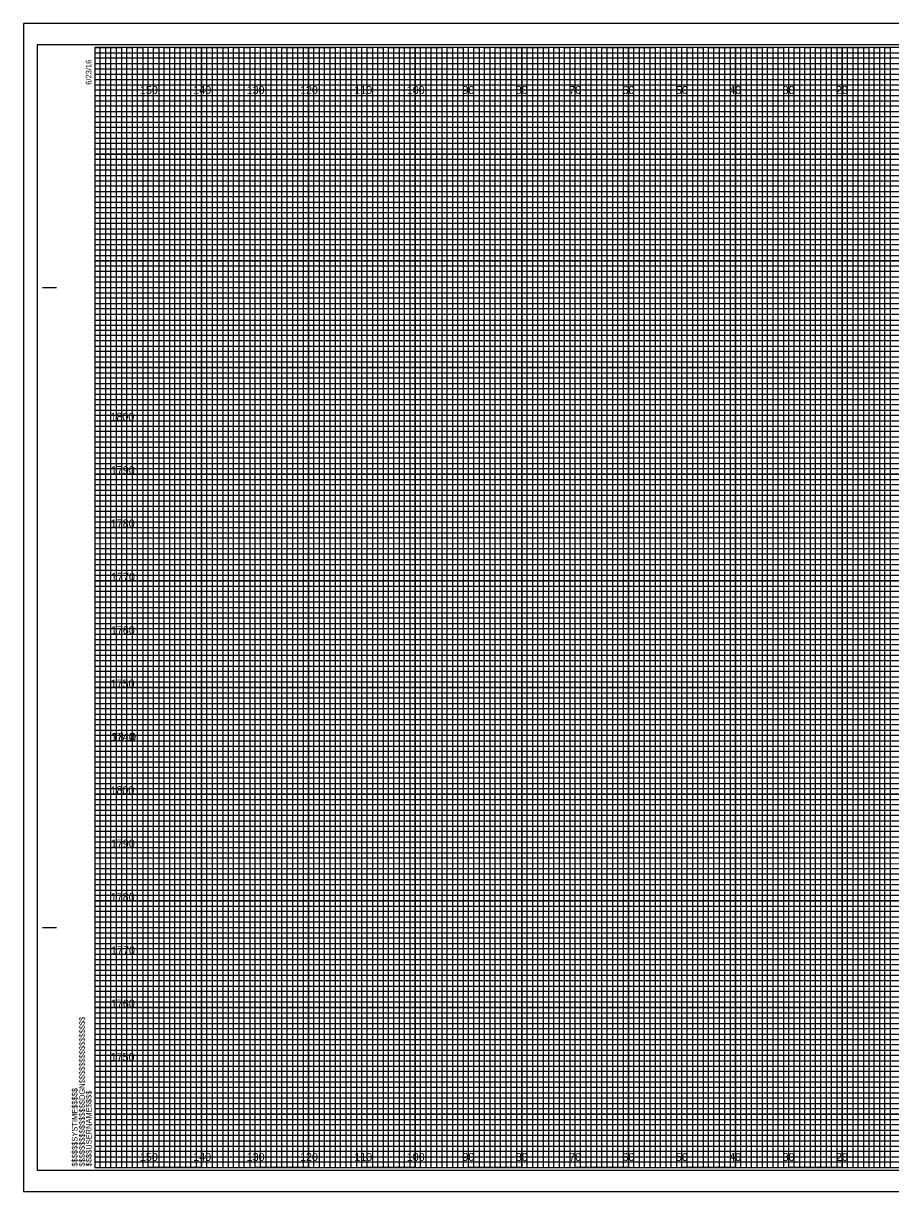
# Model space of a CAD drawing. Extents: x -15 to 323, y -5 to 6170.
# Drawn here: x -13.4 to 149.1, y 3515.5 to 3734.5 of the extents above; entities that cross this region are included whole.
import ezdxf

# ---------------------------------------------------------------- set-up
doc = ezdxf.new("R2010")
doc.units = 0
for name, color, linetype in [('Prop XS DDE', 7, 'Continuous'), ('Prop XS DDE Slope Text', 7, 'Continuous'), ('Prop XS DDE Text', 7, 'Continuous'), ('Prop XS Earthwork Shape', 7, 'Continuous'), ('Prop XS Noise Wall', 7, 'Continuous'), ('Prop XS Retaining Wall', 7, 'Continuous'), ('Prop XS Station Labels', 7, 'Continuous'), ('Scratch_Level_3', 7, 'Continuous'), ('Scratch_Level_7', 7, 'Continuous'), ('Scratch_Level_8', 7, 'Continuous'), ('Sheet Cross Section Grid Minor 1 CELL', 7, 'Continuous')]:
    doc.layers.add(name, color=color, linetype=linetype)

msp = doc.modelspace()

# ---------------------------------------------------------------- linework, layer by layer
at = {"layer": 'Prop XS DDE'}
msp.add_lwpolyline([(-13.4, 3515.5), (323.3, 3515.5), (323.3, 3734.5), (-13.4, 3734.5)], close=True, dxfattribs=at)
at = {"layer": 'Prop XS DDE Slope Text'}
msp.add_lwpolyline([(-10.8, 3519.5), (322.4, 3519.5), (322.4, 3730.5), (-10.8, 3730.5)], close=True, dxfattribs=at)
at = {"layer": 'Prop XS DDE Text'}
for p, q in [((10, 3520), (10, 3730)), ((20, 3520), (20, 3730)), ((30, 3520), (30, 3730)), ((40, 3520), (40, 3730)), ((50, 3520), (50, 3730)), ((60, 3520), (60, 3730)), ((70, 3520), (70, 3730)), ((80, 3520), (80, 3730)), ((90, 3520), (90, 3730)), ((100, 3520), (100, 3730)), ((110, 3520), (110, 3730)), ((120, 3520), (120, 3730)), ((130, 3520), (130, 3730)), ((140, 3520), (140, 3730)), ((0, 3720), (320, 3720)), ((0, 3710), (320, 3710)), ((0, 3700), (320, 3700)), ((0, 3690), (320, 3690)), ((0, 3680), (320, 3680)), ((0, 3670), (320, 3670)), ((0, 3660), (320, 3660)), ((0, 3650), (320, 3650)), ((0, 3640), (320, 3640)), ((0, 3630), (320, 3630)), ((0, 3620), (320, 3620)), ((0, 3610), (320, 3610)), ((0, 3600), (320, 3600)), ((0, 3590), (320, 3590)), ((0, 3580), (320, 3580)), ((0, 3570), (320, 3570)), ((0, 3560), (320, 3560)), ((0, 3550), (320, 3550)), ((0, 3540), (320, 3540)), ((0, 3530), (320, 3530))]:
    msp.add_line(p, q, dxfattribs=at)
at = {"layer": 'Prop XS Earthwork Shape'}
for p, q in [((10, 3730), (0, 3730)), ((10, 3520), (10, 3730)), ((30, 3730), (20, 3730)), ((20, 3730), (20, 3520)), ((30, 3520), (30, 3730)), ((50, 3730), (40, 3730)), ((40, 3730), (40, 3520)), ((50, 3520), (50, 3730)), ((70, 3730), (60, 3730)), ((60, 3730), (60, 3520)), ((70, 3520), (70, 3730)), ((90, 3730), (80, 3730)), ((80, 3730), (80, 3520)), ((90, 3520), (90, 3730)), ((110, 3730), (100, 3730)), ((100, 3730), (100, 3520)), ((110, 3520), (110, 3730)), ((130, 3730), (120, 3730)), ((120, 3730), (120, 3520)), ((130, 3520), (130, 3730)), ((150, 3730), (140, 3730)), ((140, 3730), (140, 3520)), ((20, 3520), (10, 3520)), ((40, 3520), (30, 3520)), ((60, 3520), (50, 3520)), ((80, 3520), (70, 3520)), ((100, 3520), (90, 3520)), ((120, 3520), (110, 3520)), ((140, 3520), (130, 3520))]:
    msp.add_line(p, q, dxfattribs=at)
for points in [[(0, 3720), (320, 3720), (320, 3710), (0, 3710)], [(0, 3700), (320, 3700), (320, 3690), (0, 3690)], [(0, 3680), (320, 3680), (320, 3670), (0, 3670)], [(0, 3660), (320, 3660), (320, 3650), (0, 3650)], [(0, 3640), (320, 3640), (320, 3630), (0, 3630)], [(0, 3620), (320, 3620), (320, 3610), (0, 3610)], [(0, 3600), (320, 3600), (320, 3590), (0, 3590)], [(0, 3580), (320, 3580), (320, 3570), (0, 3570)], [(0, 3560), (320, 3560), (320, 3550), (0, 3550)], [(0, 3540), (320, 3540), (320, 3530), (0, 3530)]]:
    msp.add_lwpolyline(points, dxfattribs=at)
at = {"layer": 'Prop XS Noise Wall'}
for p, q in [((-9.8, 3685), (-7.3, 3685)), ((-9.7, 3685), (-7.2, 3685)), ((-9.8, 3565), (-7.3, 3565)), ((-9.7, 3565), (-7.2, 3565)), ((0, 3520), (0, 3520)), ((0, 3520), (0, 3520)), ((0, 3520), (0, 3520)), ((0, 3520), (0, 3520)), ((0, 3520), (0, 3520)), ((0, 3520), (0, 3520)), ((0, 3520), (0, 3520))]:
    msp.add_line(p, q, dxfattribs=at)
msp.add_lwpolyline([(320, 3730), (0, 3730), (0, 3520), (320, 3520)], close=True, dxfattribs=at)
at = {"layer": 'Prop XS Retaining Wall'}
for points in [[(0, 3520), (1, 3520), (1, 3730), (2, 3730), (2, 3520)], [(2, 3520), (3, 3520), (3, 3730), (4, 3730), (4, 3520)], [(5, 3520), (6, 3520), (6, 3730), (7, 3730), (7, 3520)], [(7, 3520), (8, 3520), (8, 3730), (9, 3730), (9, 3520)], [(10, 3520), (11, 3520), (11, 3730), (12, 3730), (12, 3520)], [(12, 3520), (13, 3520), (13, 3730), (14, 3730), (14, 3520)], [(15, 3520), (16, 3520), (16, 3730), (17, 3730), (17, 3520)], [(17, 3520), (18, 3520), (18, 3730), (19, 3730), (19, 3520)], [(20, 3520), (21, 3520), (21, 3730), (22, 3730), (22, 3520)], [(22, 3520), (23, 3520), (23, 3730), (24, 3730), (24, 3520)], [(25, 3520), (26, 3520), (26, 3730), (27, 3730), (27, 3520)], [(27, 3520), (28, 3520), (28, 3730), (29, 3730), (29, 3520)], [(30, 3520), (31, 3520), (31, 3730), (32, 3730), (32, 3520)], [(32, 3520), (33, 3520), (33, 3730), (34, 3730), (34, 3520)], [(35, 3520), (36, 3520), (36, 3730), (37, 3730), (37, 3520)], [(37, 3520), (38, 3520), (38, 3730), (39, 3730), (39, 3520)], [(40, 3520), (41, 3520), (41, 3730), (42, 3730), (42, 3520)], [(42, 3520), (43, 3520), (43, 3730), (44, 3730), (44, 3520)], [(45, 3520), (46, 3520), (46, 3730), (47, 3730), (47, 3520)], [(47, 3520), (48, 3520), (48, 3730), (49, 3730), (49, 3520)], [(50, 3520), (51, 3520), (51, 3730), (52, 3730), (52, 3520)], [(52, 3520), (53, 3520), (53, 3730), (54, 3730), (54, 3520)], [(55, 3520), (56, 3520), (56, 3730), (57, 3730), (57, 3520)], [(57, 3520), (58, 3520), (58, 3730), (59, 3730), (59, 3520)], [(60, 3520), (61, 3520), (61, 3730), (62, 3730), (62, 3520)], [(62, 3520), (63, 3520), (63, 3730), (64, 3730), (64, 3520)], [(65, 3520), (66, 3520), (66, 3730), (67, 3730), (67, 3520)], [(67, 3520), (68, 3520), (68, 3730), (69, 3730), (69, 3520)], [(70, 3520), (71, 3520), (71, 3730), (72, 3730), (72, 3520)], [(72, 3520), (73, 3520), (73, 3730), (74, 3730), (74, 3520)], [(75, 3520), (76, 3520), (76, 3730), (77, 3730), (77, 3520)], [(77, 3520), (78, 3520), (78, 3730), (79, 3730), (79, 3520)], [(80, 3520), (81, 3520), (81, 3730), (82, 3730), (82, 3520)], [(82, 3520), (83, 3520), (83, 3730), (84, 3730), (84, 3520)], [(85, 3520), (86, 3520), (86, 3730), (87, 3730), (87, 3520)], [(87, 3520), (88, 3520), (88, 3730), (89, 3730), (89, 3520)], [(90, 3520), (91, 3520), (91, 3730), (92, 3730), (92, 3520)], [(92, 3520), (93, 3520), (93, 3730), (94, 3730), (94, 3520)], [(95, 3520), (96, 3520), (96, 3730), (97, 3730), (97, 3520)], [(97, 3520), (98, 3520), (98, 3730), (99, 3730), (99, 3520)], [(100, 3520), (101, 3520), (101, 3730), (102, 3730), (102, 3520)], [(102, 3520), (103, 3520), (103, 3730), (104, 3730), (104, 3520)], [(105, 3520), (106, 3520), (106, 3730), (107, 3730), (107, 3520)], [(107, 3520), (108, 3520), (108, 3730), (109, 3730), (109, 3520)], [(110, 3520), (111, 3520), (111, 3730), (112, 3730), (112, 3520)], [(112, 3520), (113, 3520), (113, 3730), (114, 3730), (114, 3520)], [(115, 3520), (116, 3520), (116, 3730), (117, 3730), (117, 3520)], [(117, 3520), (118, 3520), (118, 3730), (119, 3730), (119, 3520)], [(120, 3520), (121, 3520), (121, 3730), (122, 3730), (122, 3520)], [(122, 3520), (123, 3520), (123, 3730), (124, 3730), (124, 3520)], [(125, 3520), (126, 3520), (126, 3730), (127, 3730), (127, 3520)], [(127, 3520), (128, 3520), (128, 3730), (129, 3730), (129, 3520)], [(130, 3520), (131, 3520), (131, 3730), (132, 3730), (132, 3520)], [(132, 3520), (133, 3520), (133, 3730), (134, 3730), (134, 3520)], [(135, 3520), (136, 3520), (136, 3730), (137, 3730), (137, 3520)], [(137, 3520), (138, 3520), (138, 3730), (139, 3730), (139, 3520)], [(140, 3520), (141, 3520), (141, 3730), (142, 3730), (142, 3520)], [(142, 3520), (143, 3520), (143, 3730), (144, 3730), (144, 3520)], [(145, 3520), (146, 3520), (146, 3730), (147, 3730), (147, 3520)], [(147, 3520), (148, 3520), (148, 3730), (149, 3730), (149, 3520)]]:
    msp.add_lwpolyline(points, dxfattribs=at)
at = {"layer": 'Prop XS Station Labels'}
for points in [[(0, 3730), (5, 3730), (5, 3520), (15, 3520), (15, 3730), (25, 3730), (25, 3520), (35, 3520), (35, 3730), (45, 3730), (45, 3520), (55, 3520), (55, 3730), (65, 3730), (65, 3520), (75, 3520), (75, 3730), (85, 3730), (85, 3520), (95, 3520), (95, 3730), (105, 3730), (105, 3520), (115, 3520), (115, 3730), (125, 3730), (125, 3520), (135, 3520), (135, 3730), (145, 3730), (145, 3520), (155, 3520)], [(0, 3725), (275, 3725)], [(0, 3705), (320, 3705), (320, 3715), (0, 3715)], [(0, 3685), (320, 3685), (320, 3695), (0, 3695)], [(0, 3665), (320, 3665), (320, 3675), (0, 3675)], [(0, 3645), (320, 3645), (320, 3655), (0, 3655)], [(0, 3625), (320, 3625), (320, 3635), (0, 3635)], [(0, 3605), (320, 3605), (320, 3615), (0, 3615)], [(0, 3585), (320, 3585), (320, 3595), (0, 3595)], [(0, 3565), (320, 3565), (320, 3575), (0, 3575)], [(0, 3545), (320, 3545), (320, 3555), (0, 3555)], [(0, 3525), (320, 3525), (320, 3535), (0, 3535)]]:
    msp.add_lwpolyline(points, dxfattribs=at)
at = {"layer": 'Scratch_Level_7'}
for p, q in [((323.3, 3734.5), (-13.4, 3734.5)), ((-13.4, 3734.5), (-13.4, 3515.5)), ((-13.4, 3515.5), (323.3, 3515.5))]:
    msp.add_line(p, q, dxfattribs=at)
at = {"layer": 'Sheet Cross Section Grid Minor 1 CELL'}
for p, q in [((0, 3729), (260, 3729)), ((260, 3727.98), (0, 3727.98)), ((0, 3727.98), (0, 3727)), ((0, 3727), (260, 3727)), ((260, 3725.89), (0, 3725.89)), ((0, 3725.89), (0, 3724)), ((0, 3724), (320, 3724))]:
    msp.add_line(p, q, dxfattribs=at)
for points in [[(0, 3723), (270, 3723), (320, 3723), (320, 3722), (0, 3722)], [(0, 3721), (320, 3721), (320, 3719), (0, 3719)], [(0, 3718), (320, 3718), (320, 3717), (0, 3716.98)], [(0, 3716), (320, 3716), (320, 3714), (0, 3714)], [(0, 3713), (320, 3713), (320, 3712), (0, 3712)], [(0, 3711), (320, 3711), (320, 3709), (0, 3709)], [(0, 3708), (320, 3708), (320, 3707), (0, 3707)], [(0, 3706), (320, 3706), (320, 3704), (0, 3704)], [(0, 3703), (320, 3703), (320, 3702), (0, 3702)], [(0, 3701), (320, 3701), (320, 3699), (0, 3699)], [(0, 3698), (320, 3698), (320, 3697), (0, 3697)], [(0, 3696), (320, 3696), (320, 3693.95), (320, 3693), (320, 3692), (0, 3692)], [(0, 3694), (320, 3694), (320, 3693), (0, 3693)], [(0, 3691), (320, 3691), (320, 3689), (0, 3689.03)], [(0, 3689.03), (320, 3689), (320, 3688), (0, 3688)], [(0, 3687), (320, 3687), (320, 3686), (0, 3686)], [(0, 3684), (320, 3684), (320, 3683), (0, 3683)], [(0, 3682), (320, 3682), (320, 3681), (0, 3681)], [(-0.07, 3678.89), (320, 3678.89), (320, 3677.88), (-0.07, 3677.88)], [(0, 3677), (320, 3677), (320, 3676), (0, 3676)], [(0, 3674), (320, 3674), (320, 3673), (0, 3673)], [(0, 3672), (320, 3672), (320, 3671), (0, 3671)], [(0, 3669), (320, 3669), (320, 3668), (0, 3668)], [(0, 3667), (320, 3667), (320, 3666), (0, 3666)], [(0, 3664), (320, 3664), (320, 3663), (0, 3663)], [(0, 3662), (320, 3662), (320, 3661), (0, 3661)], [(0, 3659), (320, 3659), (319.99, 3657.98), (0, 3658)], [(0, 3657), (320, 3657), (320, 3656), (0, 3656)], [(0, 3654), (320, 3654), (320, 3653), (0, 3653)], [(0, 3652), (320, 3652), (320, 3651), (0, 3651)], [(0, 3649), (320, 3649), (320, 3648), (0, 3648)], [(0, 3647), (320, 3647), (320, 3646), (0, 3646)], [(0, 3644), (320, 3644), (320, 3643), (0, 3643)], [(0, 3642), (320, 3642), (320, 3641), (0, 3641)], [(0, 3639), (320, 3639), (320, 3638), (0, 3638)], [(0, 3636.99), (320.07, 3636.91), (320, 3636), (0, 3636)], [(0, 3634), (320, 3634), (320, 3633), (0, 3633)], [(0, 3632), (320, 3632), (320, 3631), (0, 3631)], [(0, 3629), (320, 3629), (320, 3628), (0, 3628)], [(0, 3627), (320, 3627), (320, 3626), (0, 3626)], [(0, 3624), (320, 3624), (320, 3623), (0, 3623)], [(0, 3622), (320, 3622), (320, 3621), (0, 3621)], [(0, 3619), (320, 3619), (320, 3618), (0, 3618)], [(0, 3617), (320, 3617), (320, 3616), (0, 3616)], [(0, 3614), (320, 3614), (320, 3613), (0, 3613)], [(0, 3612), (320, 3612), (320, 3611), (0, 3611)], [(0, 3609), (320, 3609), (320, 3608), (0, 3608)], [(0, 3607), (320, 3607), (320, 3606), (0, 3606)], [(0, 3604), (320, 3604), (320, 3603), (0, 3603)], [(0, 3602), (320, 3602), (320, 3601), (0, 3601)], [(0, 3599), (320, 3599), (319.99, 3597.98), (0, 3598)], [(0, 3597), (320, 3597), (320, 3596), (0, 3596)], [(0, 3594), (320, 3594), (320, 3593), (0, 3593)], [(0, 3592), (320, 3592), (320, 3591), (0, 3591)], [(0, 3589), (320, 3589), (320, 3588), (0, 3588)], [(0, 3587), (320, 3587), (320, 3586), (0, 3586)], [(0, 3584), (320, 3584), (320, 3583), (0, 3583)], [(0, 3582), (320, 3582), (320, 3581), (0, 3581)], [(0, 3579), (320, 3579), (320, 3578), (0, 3578)], [(0, 3576.99), (320.07, 3576.91), (320, 3576), (0, 3576)], [(0, 3574), (320, 3574), (320, 3573), (0, 3573)], [(0, 3572), (320, 3572), (320, 3571), (0, 3571)], [(0, 3569), (320, 3569), (320, 3568), (0, 3568)], [(0, 3567), (320, 3567), (320, 3566), (0, 3566)], [(0, 3564), (320, 3564), (320, 3563), (0, 3563)], [(0, 3562), (320, 3562), (320, 3561), (0, 3561)], [(0, 3559), (320, 3559), (320, 3558), (0, 3558)], [(0, 3557), (320, 3557), (320, 3556), (0, 3556)], [(0, 3554), (320, 3554), (320, 3553), (0, 3553)], [(0, 3552), (320, 3552), (320, 3551), (0, 3551)], [(0, 3549), (320, 3549), (320, 3548), (0, 3548)], [(0, 3547), (320, 3547), (320, 3546), (0, 3546)], [(0, 3544), (320, 3544), (320, 3543), (0, 3543)], [(0, 3542), (320, 3542), (320, 3541), (0, 3541)], [(0, 3539), (320, 3539), (320, 3538), (0, 3538)], [(0, 3537), (320, 3537), (320, 3536), (0, 3536)], [(0, 3534), (320, 3534), (320, 3533), (0, 3533)], [(0, 3532), (320, 3532), (320, 3531), (0, 3531)], [(0, 3529), (320, 3529), (320, 3528), (0, 3528)], [(0, 3527), (320, 3527), (320, 3526), (0, 3526)], [(0, 3524), (320, 3524), (320, 3523), (0, 3523)], [(0, 3522), (320, 3522), (320, 3521), (0, 3521)]]:
    msp.add_lwpolyline(points, dxfattribs=at)

# ---------------------------------------------------------------- texts
at = {"layer": 'Prop XS Noise Wall'}
for s, p in [('6/23/16', (-0.65, 3723)), ('$$$$$$$$$$$$$$$$DGN$$$$$$$$$$$$$$$$', (-1.88, 3520.18)), ('$$$$$$SYSTIME$$$$$', (-3.26, 3520.18)), ('$$$$USERNAME$$$$', (-0.62, 3520.23))]:
    msp.add_text(s, height=1.05, rotation=90, dxfattribs=at).set_placement(p)
at = {"layer": 'Scratch_Level_3'}
for s, p in [('1800', (2.92, 3660)), ('1790', (3, 3650)), ('1780', (2.98, 3640)), ('1770', (3.04, 3630)), ('1760', (3, 3620)), ('1750', (2.96, 3610)), ('1740', (3, 3600)), ('1810', (3.25, 3600)), ('1800', (2.92, 3590)), ('1790', (3, 3580)), ('1780', (2.98, 3570)), ('1770', (3.04, 3560)), ('1760', (3, 3550)), ('1750', (2.96, 3540))]:
    msp.add_text(s, height=1.5, dxfattribs=at).set_placement(p)
at = {"layer": 'Scratch_Level_8'}
for s, p in [('150', (8.44, 3721.25)), ('140', (18.44, 3721.25)), ('130', (28.44, 3721.25)), ('120', (38.44, 3721.25)), ('110', (48.62, 3721.25)), ('100', (58.44, 3721.25)), ('90', (68.86, 3721.25)), ('80', (78.86, 3721.25)), ('70', (88.86, 3721.25)), ('60', (98.86, 3721.25)), ('50', (108.86, 3721.25)), ('40', (118.86, 3721.25)), ('30', (128.86, 3721.25)), ('20', (138.86, 3721.25)), ('150', (8.44, 3521.25)), ('140', (18.44, 3521.25)), ('130', (28.44, 3521.25)), ('120', (38.44, 3521.25)), ('110', (48.62, 3521.25)), ('100', (58.44, 3521.25)), ('90', (68.86, 3521.25)), ('80', (78.86, 3521.25)), ('70', (88.86, 3521.25)), ('60', (98.86, 3521.25)), ('50', (108.86, 3521.25)), ('40', (118.86, 3521.25)), ('30', (128.86, 3521.25)), ('20', (138.86, 3521.25))]:
    msp.add_text(s, height=1.5, dxfattribs=at).set_placement(p)

doc.saveas('drawing.dxf')
